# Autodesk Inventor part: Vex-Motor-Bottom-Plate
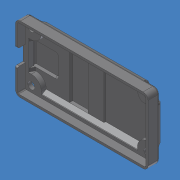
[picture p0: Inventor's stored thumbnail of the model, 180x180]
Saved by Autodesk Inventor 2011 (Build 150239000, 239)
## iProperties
Created: 2007-08
Part Number: Vex-Motor-Bottom-Plate
Material: ABS Plastic
Document SubType Name: Modeling
Density: 1.06 g/cm^3
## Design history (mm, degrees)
feature "Base1"
body "Solid1"
